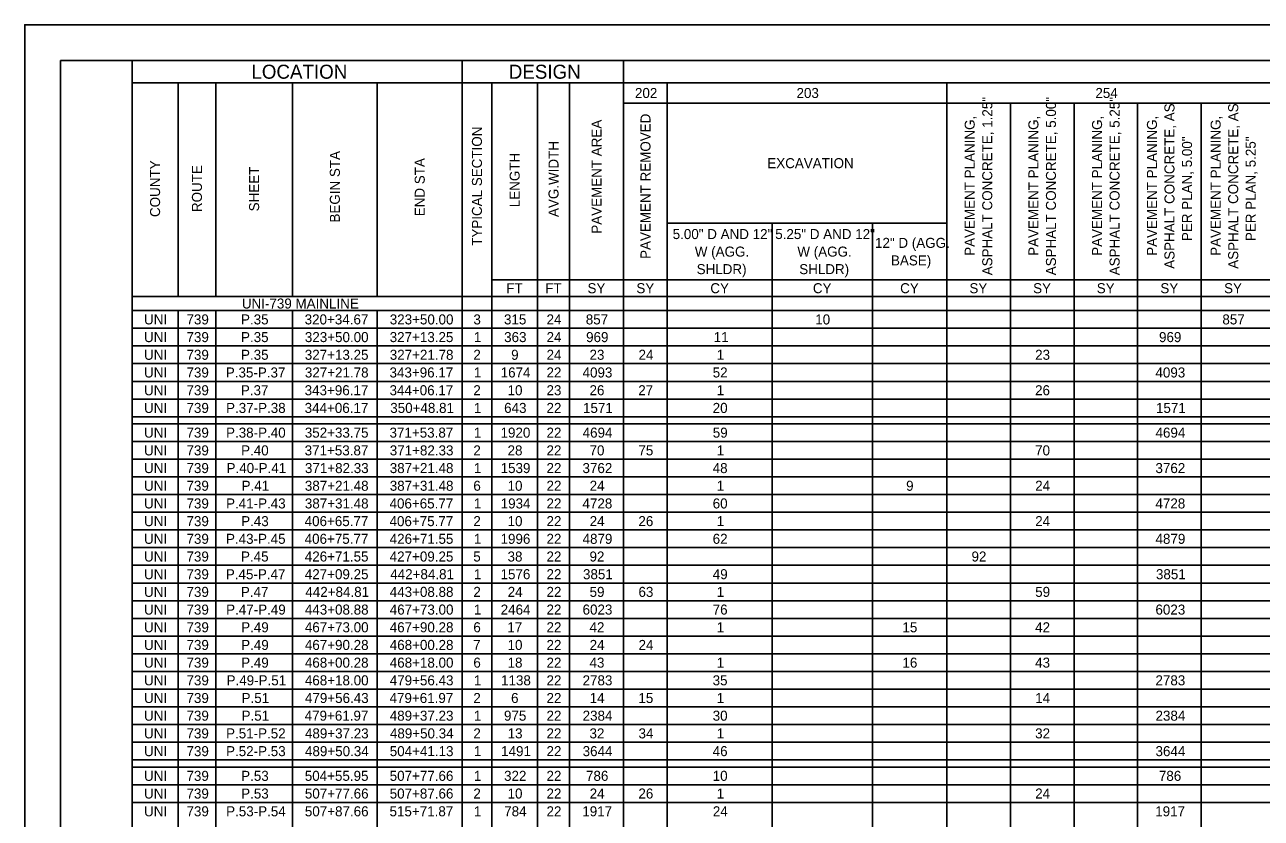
# Model space of a CAD drawing. Extents: x 0 to 34, y 0 to 22.
# Drawn here: x 0 to 17.28, y 10.92 to 22 of the extents above; entities that cross this region are included whole.
import ezdxf

# ---------------------------------------------------------------- set-up
doc = ezdxf.new("R2010")
doc.units = 0
for name, color, linetype in [('SH_Border', 7, 'Continuous'), ('SH_Cut_Line', 7, 'Continuous'), ('SH_Text', 7, 'Continuous')]:
    doc.layers.add(name, color=color, linetype=linetype)

msp = doc.modelspace()

# ---------------------------------------------------------------- linework, layer by layer
at = {"layer": 'SH_Border'}
for points in [[(0.5, 21.5), (1.5, 21.5), (1.5, 0.5), (0.5, 0.5)], [(1.5, 21.5), (33.5, 21.5), (33.5, 0.5), (1.5, 0.5)]]:
    msp.add_lwpolyline(points, close=True, dxfattribs=at)
at = {"layer": 'SH_Cut_Line'}
msp.add_lwpolyline([(0, 0), (34, 0), (34, 22), (0, 22)], close=True, dxfattribs=at)
at = {"layer": 'SH_Text'}
for p, q in [((1.5, 21.5), (31.971, 21.5)), ((6.112, 21.5), (6.112, 0.813)), ((8.368, 21.5), (8.368, 0.516)), ((1.5, 21.187), (31.971, 21.187)), ((1.5, 21.187), (1.5, 0.813)), ((2.142, 21.187), (2.142, 18.206)), ((2.669, 21.187), (2.669, 18.206)), ((3.74, 21.187), (3.74, 18.206)), ((4.926, 21.187), (4.926, 18.206)), ((6.524, 21.187), (6.524, 0.813)), ((7.166, 21.187), (7.166, 0.813)), ((7.611, 21.187), (7.611, 0.813)), ((8.978, 21.187), (8.978, 0.516)), ((12.881, 21.187), (12.881, 0.516)), ((8.368, 20.907), (31.971, 20.907)), ((13.771, 20.907), (13.771, 0.516)), ((14.66, 20.907), (14.66, 0.516)), ((15.549, 20.907), (15.549, 0.516)), ((16.439, 20.907), (16.439, 0.516)), ((8.978, 19.227), (12.881, 19.227)), ((10.444, 19.227), (10.444, 0.813)), ((11.844, 19.227), (11.844, 0.813)), ((6.524, 18.436), (31.971, 18.436)), ((1.5, 18.206), (31.971, 18.206)), ((1.5, 18.008), (31.971, 18.008)), ((2.142, 18.008), (2.142, 0.813)), ((2.669, 18.008), (2.669, 0.813)), ((3.74, 18.008), (3.74, 0.813)), ((4.926, 18.008), (4.926, 0.813)), ((1.5, 17.761), (31.971, 17.761)), ((1.5, 17.514), (31.971, 17.514)), ((1.5, 17.267), (31.971, 17.267)), ((1.5, 17.02), (31.971, 17.02)), ((1.5, 16.773), (31.971, 16.773)), ((1.5, 16.526), (31.971, 16.526)), ((1.5, 16.427), (31.971, 16.427)), ((1.5, 16.18), (31.971, 16.18)), ((1.5, 15.933), (31.971, 15.933)), ((1.5, 15.686), (31.971, 15.686)), ((1.5, 15.439), (31.971, 15.439)), ((1.5, 15.192), (31.971, 15.192)), ((1.5, 14.945), (31.971, 14.945)), ((1.5, 14.698), (31.971, 14.698)), ((1.5, 14.451), (31.971, 14.451)), ((1.5, 14.204), (31.971, 14.204)), ((1.5, 13.956), (31.971, 13.956)), ((1.5, 13.709), (31.971, 13.709)), ((1.5, 13.462), (31.971, 13.462)), ((1.5, 13.215), (31.971, 13.215)), ((1.5, 12.968), (31.971, 12.968)), ((1.5, 12.721), (31.971, 12.721)), ((1.5, 12.474), (31.971, 12.474)), ((1.5, 12.227), (31.971, 12.227)), ((1.5, 11.98), (31.971, 11.98)), ((1.5, 11.733), (31.971, 11.733)), ((1.5, 11.634), (31.971, 11.634)), ((1.5, 11.387), (31.971, 11.387)), ((1.5, 11.14), (31.971, 11.14))]:
    msp.add_line(p, q, dxfattribs=at)

# ---------------------------------------------------------------- texts
for s, height, p in [('LOCATION', 0.196, (3.167, 21.246)), ('DESIGN', 0.196, (6.763, 21.246)), ('202', 0.14, (8.526, 20.977)), ('203', 0.14, (10.783, 20.977)), ('254', 0.14, (14.959, 20.977)), ('EXCAVATION', 0.14, (10.375, 19.997)), ('5.00" D AND 12" ', 0.14, (9.053, 19.007)), ('5.25" D AND 12" ', 0.14, (10.486, 19.007)), ('12" D (AGG. ', 0.14, (11.88, 18.884)), ('W (AGG. ', 0.14, (9.362, 18.762)), ('W (AGG. ', 0.14, (10.795, 18.762)), ('SHLDR)', 0.14, (9.388, 18.517)), ('SHLDR)', 0.14, (10.821, 18.517)), ('BASE)', 0.14, (12.103, 18.639)), ('FT', 0.14, (6.728, 18.251)), ('FT', 0.14, (7.272, 18.251)), ('SY', 0.14, (7.863, 18.251)), ('SY', 0.14, (8.546, 18.251)), ('CY', 0.14, (9.579, 18.251)), ('CY', 0.14, (11.012, 18.251)), ('CY', 0.14, (12.231, 18.251)), ('SY', 0.14, (13.199, 18.251)), ('SY', 0.14, (14.089, 18.251)), ('SY', 0.14, (14.978, 18.251)), ('SY', 0.14, (15.867, 18.251)), ('SY', 0.14, (16.757, 18.251)), ('UNI-739 MAINLINE', 0.14, (3.034, 18.037)), ('UNI', 0.14, (1.667, 17.815)), ('739', 0.14, (2.26, 17.815)), ('P.35', 0.14, (3.022, 17.815)), ('320+34.67', 0.14, (3.911, 17.815)), ('323+50.00', 0.14, (5.1, 17.815)), ('3', 0.14, (6.269, 17.815)), ('315', 0.14, (6.696, 17.815)), ('24', 0.14, (7.291, 17.815)), ('857', 0.14, (7.839, 17.815)), ('10', 0.14, (11.045, 17.815)), ('857', 0.14, (16.733, 17.815)), ('UNI', 0.14, (1.667, 17.568)), ('739', 0.14, (2.26, 17.568)), ('P.35', 0.14, (3.022, 17.568)), ('323+50.00', 0.14, (3.914, 17.568)), ('327+13.25', 0.14, (5.099, 17.568)), ('1', 0.14, (6.275, 17.568)), ('363', 0.14, (6.698, 17.568)), ('24', 0.14, (7.291, 17.568)), ('969', 0.14, (7.843, 17.568)), ('11', 0.14, (9.626, 17.568)), ('969', 0.14, (15.848, 17.568)), ('UNI', 0.14, (1.667, 17.321)), ('739', 0.14, (2.26, 17.321)), ('P.35', 0.14, (3.022, 17.321)), ('327+13.25', 0.14, (3.913, 17.321)), ('327+21.78', 0.14, (5.1, 17.321)), ('2', 0.14, (6.268, 17.321)), ('9', 0.14, (6.796, 17.321)), ('24', 0.14, (7.291, 17.321)), ('23', 0.14, (7.891, 17.321)), ('24', 0.14, (8.576, 17.321)), ('1', 0.14, (9.668, 17.321)), ('23', 0.14, (14.117, 17.321)), ('UNI', 0.14, (1.667, 17.074)), ('739', 0.14, (2.26, 17.074)), ('P.35-P.37', 0.14, (2.81, 17.074)), ('327+21.78', 0.14, (3.914, 17.074)), ('343+96.17', 0.14, (5.097, 17.074)), ('1', 0.14, (6.275, 17.074)), ('1674', 0.14, (6.65, 17.074)), ('22', 0.14, (7.29, 17.074)), ('4093', 0.14, (7.794, 17.074)), ('52', 0.14, (9.612, 17.074)), ('4093', 0.14, (15.798, 17.074)), ('UNI', 0.14, (1.667, 16.826)), ('739', 0.14, (2.26, 16.826)), ('P.37', 0.14, (3.02, 16.826)), ('343+96.17', 0.14, (3.911, 16.826)), ('344+06.17', 0.14, (5.097, 16.826)), ('2', 0.14, (6.268, 16.826)), ('10', 0.14, (6.746, 16.826)), ('23', 0.14, (7.29, 16.826)), ('26', 0.14, (7.891, 16.826)), ('27', 0.14, (8.572, 16.826)), ('1', 0.14, (9.668, 16.826)), ('26', 0.14, (14.116, 16.826)), ('UNI', 0.14, (1.667, 16.579)), ('739', 0.14, (2.26, 16.579)), ('P.37-P.38', 0.14, (2.813, 16.579)), ('344+06.17', 0.14, (3.911, 16.579)), ('350+48.81', 0.14, (5.107, 16.579)), ('1', 0.14, (6.275, 16.579)), ('643', 0.14, (6.698, 16.579)), ('22', 0.14, (7.29, 16.579)), ('1571', 0.14, (7.8, 16.579)), ('20', 0.14, (9.612, 16.579)), ('1571', 0.14, (15.805, 16.579)), ('UNI', 0.14, (1.667, 16.234)), ('739', 0.14, (2.26, 16.234)), ('P.38-P.40', 0.14, (2.813, 16.234)), ('352+33.75', 0.14, (3.913, 16.234)), ('371+53.87', 0.14, (5.097, 16.234)), ('1', 0.14, (6.275, 16.234)), ('1920', 0.14, (6.648, 16.234)), ('22', 0.14, (7.29, 16.234)), ('4694', 0.14, (7.795, 16.234)), ('59', 0.14, (9.613, 16.234)), ('4694', 0.14, (15.799, 16.234)), ('UNI', 0.14, (1.667, 15.986)), ('739', 0.14, (2.26, 15.986)), ('P.40', 0.14, (3.023, 15.986)), ('371+53.87', 0.14, (3.911, 15.986)), ('371+82.33', 0.14, (5.1, 15.986)), ('2', 0.14, (6.268, 15.986)), ('28', 0.14, (6.746, 15.986)), ('22', 0.14, (7.29, 15.986)), ('70', 0.14, (7.891, 15.986)), ('75', 0.14, (8.574, 15.986)), ('1', 0.14, (9.668, 15.986)), ('70', 0.14, (14.117, 15.986)), ('UNI', 0.14, (1.667, 15.739)), ('739', 0.14, (2.26, 15.739)), ('P.40-P.41', 0.14, (2.82, 15.739)), ('371+82.33', 0.14, (3.915, 15.739)), ('387+21.48', 0.14, (5.1, 15.739)), ('1', 0.14, (6.275, 15.739)), ('1539', 0.14, (6.649, 15.739)), ('22', 0.14, (7.29, 15.739)), ('3762', 0.14, (7.793, 15.739)), ('48', 0.14, (9.612, 15.739)), ('3762', 0.14, (15.798, 15.739)), ('UNI', 0.14, (1.667, 15.492)), ('739', 0.14, (2.26, 15.492)), ('P.41', 0.14, (3.03, 15.492)), ('387+21.48', 0.14, (3.914, 15.492)), ('387+31.48', 0.14, (5.1, 15.492)), ('6', 0.14, (6.268, 15.492)), ('10', 0.14, (6.746, 15.492)), ('22', 0.14, (7.29, 15.492)), ('24', 0.14, (7.893, 15.492)), ('1', 0.14, (9.668, 15.492)), ('9', 0.14, (12.314, 15.492)), ('24', 0.14, (14.118, 15.492)), ('UNI', 0.14, (1.667, 15.245)), ('739', 0.14, (2.26, 15.245)), ('P.41-P.43', 0.14, (2.813, 15.245)), ('387+31.48', 0.14, (3.914, 15.245)), ('406+65.77', 0.14, (5.097, 15.245)), ('1', 0.14, (6.275, 15.245)), ('1934', 0.14, (6.65, 15.245)), ('22', 0.14, (7.29, 15.245)), ('4728', 0.14, (7.793, 15.245)), ('60', 0.14, (9.612, 15.245)), ('4728', 0.14, (15.798, 15.245)), ('UNI', 0.14, (1.667, 14.998)), ('739', 0.14, (2.26, 14.998)), ('P.43', 0.14, (3.024, 14.998)), ('406+65.77', 0.14, (3.911, 14.998)), ('406+75.77', 0.14, (5.097, 14.998)), ('2', 0.14, (6.268, 14.998)), ('10', 0.14, (6.746, 14.998)), ('22', 0.14, (7.29, 14.998)), ('24', 0.14, (7.893, 14.998)), ('26', 0.14, (8.574, 14.998)), ('1', 0.14, (9.668, 14.998)), ('24', 0.14, (14.118, 14.998)), ('UNI', 0.14, (1.667, 14.751)), ('739', 0.14, (2.26, 14.751)), ('P.43-P.45', 0.14, (2.812, 14.751)), ('406+75.77', 0.14, (3.911, 14.751)), ('426+71.55', 0.14, (5.099, 14.751)), ('1', 0.14, (6.275, 14.751)), ('1996', 0.14, (6.648, 14.751)), ('22', 0.14, (7.29, 14.751)), ('4879', 0.14, (7.794, 14.751)), ('62', 0.14, (9.612, 14.751)), ('4879', 0.14, (15.799, 14.751)), ('UNI', 0.14, (1.667, 14.504)), ('739', 0.14, (2.26, 14.504)), ('P.45', 0.14, (3.022, 14.504)), ('426+71.55', 0.14, (3.913, 14.504)), ('427+09.25', 0.14, (5.099, 14.504)), ('5', 0.14, (6.267, 14.504)), ('38', 0.14, (6.746, 14.504)), ('22', 0.14, (7.29, 14.504)), ('92', 0.14, (7.891, 14.504)), ('92', 0.14, (13.228, 14.504)), ('UNI', 0.14, (1.667, 14.257)), ('739', 0.14, (2.26, 14.257)), ('P.45-P.47', 0.14, (2.81, 14.257)), ('427+09.25', 0.14, (3.913, 14.257)), ('442+84.81', 0.14, (5.107, 14.257)), ('1', 0.14, (6.275, 14.257)), ('1576', 0.14, (6.648, 14.257)), ('22', 0.14, (7.29, 14.257)), ('3851', 0.14, (7.8, 14.257)), ('49', 0.14, (9.613, 14.257)), ('3851', 0.14, (15.805, 14.257)), ('UNI', 0.14, (1.667, 14.01)), ('739', 0.14, (2.26, 14.01)), ('P.47', 0.14, (3.02, 14.01)), ('442+84.81', 0.14, (3.921, 14.01)), ('443+08.88', 0.14, (5.1, 14.01)), ('2', 0.14, (6.268, 14.01)), ('24', 0.14, (6.748, 14.01)), ('22', 0.14, (7.29, 14.01)), ('59', 0.14, (7.892, 14.01)), ('63', 0.14, (8.575, 14.01)), ('1', 0.14, (9.668, 14.01)), ('59', 0.14, (14.118, 14.01)), ('UNI', 0.14, (1.667, 13.763)), ('739', 0.14, (2.26, 13.763)), ('P.47-P.49', 0.14, (2.814, 13.763)), ('443+08.88', 0.14, (3.914, 13.763)), ('467+73.00', 0.14, (5.1, 13.763)), ('1', 0.14, (6.275, 13.763)), ('2464', 0.14, (6.65, 13.763)), ('22', 0.14, (7.29, 13.763)), ('6023', 0.14, (7.794, 13.763)), ('76', 0.14, (9.612, 13.763)), ('6023', 0.14, (15.798, 13.763)), ('UNI', 0.14, (1.667, 13.516)), ('739', 0.14, (2.26, 13.516)), ('P.49', 0.14, (3.024, 13.516)), ('467+73.00', 0.14, (3.914, 13.516)), ('467+90.28', 0.14, (5.1, 13.516)), ('6', 0.14, (6.268, 13.516)), ('17', 0.14, (6.743, 13.516)), ('22', 0.14, (7.29, 13.516)), ('42', 0.14, (7.891, 13.516)), ('1', 0.14, (9.668, 13.516)), ('15', 0.14, (12.263, 13.516)), ('42', 0.14, (14.117, 13.516)), ('UNI', 0.14, (1.667, 13.269)), ('739', 0.14, (2.26, 13.269)), ('P.49', 0.14, (3.024, 13.269)), ('467+90.28', 0.14, (3.914, 13.269)), ('468+00.28', 0.14, (5.1, 13.269)), ('7', 0.14, (6.265, 13.269)), ('10', 0.14, (6.746, 13.269)), ('22', 0.14, (7.29, 13.269)), ('24', 0.14, (7.893, 13.269)), ('24', 0.14, (8.576, 13.269)), ('UNI', 0.14, (1.667, 13.022)), ('739', 0.14, (2.26, 13.022)), ('P.49', 0.14, (3.024, 13.022)), ('468+00.28', 0.14, (3.914, 13.022)), ('468+18.00', 0.14, (5.1, 13.022)), ('6', 0.14, (6.268, 13.022)), ('18', 0.14, (6.746, 13.022)), ('22', 0.14, (7.29, 13.022)), ('43', 0.14, (7.891, 13.022)), ('1', 0.14, (9.668, 13.022)), ('16', 0.14, (12.263, 13.022)), ('43', 0.14, (14.117, 13.022)), ('UNI', 0.14, (1.667, 12.775)), ('739', 0.14, (2.26, 12.775)), ('P.49-P.51', 0.14, (2.82, 12.775)), ('468+18.00', 0.14, (3.914, 12.775)), ('479+56.43', 0.14, (5.1, 12.775)), ('1', 0.14, (6.275, 12.775)), ('1138', 0.14, (6.655, 12.775)), ('22', 0.14, (7.29, 12.775)), ('2783', 0.14, (7.794, 12.775)), ('35', 0.14, (9.611, 12.775)), ('2783', 0.14, (15.798, 12.775)), ('UNI', 0.14, (1.667, 12.528)), ('739', 0.14, (2.26, 12.528)), ('P.51', 0.14, (3.03, 12.528)), ('479+56.43', 0.14, (3.915, 12.528)), ('479+61.97', 0.14, (5.097, 12.528)), ('2', 0.14, (6.268, 12.528)), ('6', 0.14, (6.795, 12.528)), ('22', 0.14, (7.29, 12.528)), ('14', 0.14, (7.893, 12.528)), ('15', 0.14, (8.574, 12.528)), ('1', 0.14, (9.668, 12.528)), ('14', 0.14, (14.118, 12.528)), ('UNI', 0.14, (1.667, 12.281)), ('739', 0.14, (2.26, 12.281)), ('P.51', 0.14, (3.03, 12.281)), ('479+61.97', 0.14, (3.911, 12.281)), ('489+37.23', 0.14, (5.1, 12.281)), ('1', 0.14, (6.275, 12.281)), ('975', 0.14, (6.696, 12.281)), ('22', 0.14, (7.29, 12.281)), ('2384', 0.14, (7.795, 12.281)), ('30', 0.14, (9.612, 12.281)), ('2384', 0.14, (15.799, 12.281)), ('UNI', 0.14, (1.667, 12.034)), ('739', 0.14, (2.26, 12.034)), ('P.51-P.52', 0.14, (2.813, 12.034)), ('489+37.23', 0.14, (3.915, 12.034)), ('489+50.34', 0.14, (5.102, 12.034)), ('2', 0.14, (6.268, 12.034)), ('13', 0.14, (6.747, 12.034)), ('22', 0.14, (7.29, 12.034)), ('32', 0.14, (7.891, 12.034)), ('34', 0.14, (8.576, 12.034)), ('1', 0.14, (9.668, 12.034)), ('32', 0.14, (14.117, 12.034)), ('UNI', 0.14, (1.667, 11.786)), ('739', 0.14, (2.26, 11.786)), ('P.52-P.53', 0.14, (2.813, 11.786)), ('489+50.34', 0.14, (3.916, 11.786)), ('504+41.13', 0.14, (5.1, 11.786)), ('1', 0.14, (6.275, 11.786)), ('1491', 0.14, (6.656, 11.786)), ('22', 0.14, (7.29, 11.786)), ('3644', 0.14, (7.795, 11.786)), ('46', 0.14, (9.612, 11.786)), ('3644', 0.14, (15.799, 11.786)), ('UNI', 0.14, (1.667, 11.441)), ('739', 0.14, (2.26, 11.441)), ('P.53', 0.14, (3.024, 11.441)), ('504+55.95', 0.14, (3.913, 11.441)), ('507+77.66', 0.14, (5.099, 11.441)), ('1', 0.14, (6.275, 11.441)), ('322', 0.14, (6.697, 11.441)), ('22', 0.14, (7.29, 11.441)), ('786', 0.14, (7.842, 11.441)), ('10', 0.14, (9.612, 11.441)), ('786', 0.14, (15.846, 11.441)), ('UNI', 0.14, (1.667, 11.194)), ('739', 0.14, (2.26, 11.194)), ('P.53', 0.14, (3.024, 11.194)), ('507+77.66', 0.14, (3.914, 11.194)), ('507+87.66', 0.14, (5.099, 11.194)), ('2', 0.14, (6.268, 11.194)), ('10', 0.14, (6.746, 11.194)), ('22', 0.14, (7.29, 11.194)), ('24', 0.14, (7.893, 11.194)), ('26', 0.14, (8.574, 11.194)), ('1', 0.14, (9.668, 11.194)), ('24', 0.14, (14.118, 11.194)), ('UNI', 0.14, (1.667, 10.946)), ('739', 0.14, (2.26, 10.946)), ('P.53-P.54', 0.14, (2.814, 10.946)), ('507+87.66', 0.14, (3.914, 10.946)), ('515+71.87', 0.14, (5.097, 10.946)), ('1', 0.14, (6.275, 10.946)), ('784', 0.14, (6.699, 10.946)), ('22', 0.14, (7.29, 10.946)), ('1917', 0.14, (7.79, 10.946)), ('24', 0.14, (9.614, 10.946)), ('1917', 0.14, (15.795, 10.946))]:
    msp.add_text(s, height=height, dxfattribs=at).set_placement(p)
for s, p in [('ASPHALT CONCRETE, 1.25"', (13.518, 18.501)), ('ASPHALT CONCRETE, 5.00"', (14.408, 18.501)), ('ASPHALT CONCRETE, 5.25"', (15.297, 18.501)), ('PAVEMENT REMOVED', (8.743, 18.73)), ('ASPHALT CONCRETE, AS ', (16.064, 18.592)), ('ASPHALT CONCRETE, AS ', (16.954, 18.592)), ('TYPICAL SECTION', (6.388, 18.913)), ('PAVEMENT AREA', (8.059, 19.082)), ('PAVEMENT PLANING, ', (13.273, 18.773)), ('PAVEMENT PLANING, ', (14.163, 18.773)), ('PAVEMENT PLANING, ', (15.052, 18.773)), ('PAVEMENT PLANING, ', (15.819, 18.773)), ('PAVEMENT PLANING, ', (16.709, 18.773)), ('PER PLAN, 5.00"', (16.309, 18.979)), ('PER PLAN, 5.25"', (17.199, 18.979)), ('BEGIN STA', (4.403, 19.238)), ('AVG.WIDTH', (7.458, 19.315)), ('COUNTY', (1.891, 19.315)), ('END STA', (5.589, 19.326)), ('LENGTH', (6.915, 19.452)), ('ROUTE', (2.476, 19.384)), ('SHEET', (3.275, 19.394))]:
    msp.add_text(s, height=0.14, rotation=90, dxfattribs=at).set_placement(p)

doc.saveas('drawing.dxf')
